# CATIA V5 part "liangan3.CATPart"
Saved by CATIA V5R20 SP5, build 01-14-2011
Part number: 连杆3
Bounding box of the stored display mesh (mm): x -20 to 170, y -20 to 20, z 0 to 40
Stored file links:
  E:\scc\liangan\liangan3.CATPart
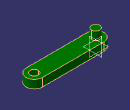
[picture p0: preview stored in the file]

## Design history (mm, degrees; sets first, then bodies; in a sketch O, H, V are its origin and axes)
Body1 (main body)
  Sketch1 on xy-plane, origin (0, 0, 0), H (1, 0, 0), V (0, 1, 0)
    construction line L1 (0, 0) -> (150, 0)
    line L2 (0, 20) -> (150, 20)
    line L3 (150, -20) -> (0, -20)
    arc A1 centre (150, 0) radius 20 from (150, 20) to (150, -20) cw
    arc A2 centre (0, 0) radius 20 from (0, -20) to (0, 20) cw
    circle A3 centre (150, 0) radius 10
    distance L1 L2 = 20
    radius A3 = 10
    horizontal: L1 H
    tangency: A1 L2, A2 L2, A1 L3, A2 L3
  Pad1: profile Sketch1, direction (0, 0, 1), length 20
  Sketch2 on end face of Pad1, origin (0, 0, 20), H (1, 0, 0), V (0, 1, 0)
    circle A1 centre (0, 0) radius 10
    radius A1 = 10
  Pad2: profile Sketch2, direction (0, 0, 1), length 20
